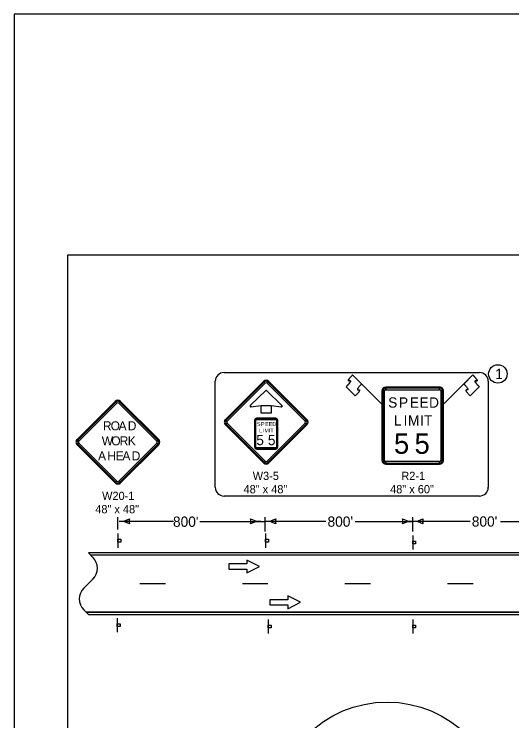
# Model space of a CAD drawing. Extents: x -2135039 to 114557, y -2139150 to -409929.
# Drawn here: x -2135039 to -2134068, y -2137945 to -2136566 of the extents above; entities that cross this region are included whole.
import ezdxf

# ---------------------------------------------------------------- set-up
doc = ezdxf.new("R2010")
doc.units = 0
for name, color, linetype in [('dsnDOTLogo', 7, 'Continuous'), ('dsnStdLabel', 7, 'Continuous'), ('dsnStdLineWork', 7, 'Continuous'), ('dsnStdNote', 7, 'Continuous'), ('dsnStdShading', 7, 'Continuous'), ('Level 1', 7, 'Continuous'), ('StdDimension', 7, 'Continuous')]:
    doc.layers.add(name, color=color, linetype=linetype)

msp = doc.modelspace()

# ---------------------------------------------------------------- linework, layer by layer
at = {"layer": 'dsnDOTLogo'}
msp.add_lwpolyline([(-2135038.9, -2139150.4), (-2131694.9, -2139150.4), (-2131694.9, -2136566.4), (-2135038.9, -2136566.4)], close=True, dxfattribs=at)
at = {"layer": 'dsnStdLabel'}
for p, q in [((-2134552.7, -2137282.5), (-2134626.9, -2137356.7)), ((-2134467.8, -2137356.7), (-2134542.1, -2137282.5)), ((-2134321.5, -2137327.3), (-2134378.8, -2137270)), ((-2134378.8, -2137270), (-2134361.1, -2137287.7)), ((-2134201.5, -2137327.3), (-2134144.2, -2137270)), ((-2134144.2, -2137270), (-2134161.9, -2137287.7)), ((-2134551.4, -2137283.8), (-2134549.2, -2137286)), ((-2134545.6, -2137286), (-2134543.4, -2137283.8)), ((-2134391.2, -2137293), (-2134373.5, -2137310.7)), ((-2134373.5, -2137310.7), (-2134391.2, -2137293)), ((-2134209, -2137293.8), (-2134314, -2137293.8)), ((-2134314, -2137298.8), (-2134314, -2137295.7)), ((-2134209, -2137295.7), (-2134209, -2137298.8)), ((-2134131.8, -2137293), (-2134149.5, -2137310.7)), ((-2134149.5, -2137310.7), (-2134131.8, -2137293)), ((-2134321.5, -2137301.3), (-2134321.5, -2137436.3)), ((-2134319.6, -2137301.3), (-2134316.5, -2137301.3)), ((-2134206.5, -2137301.3), (-2134203.4, -2137301.3)), ((-2134201.5, -2137436.3), (-2134201.5, -2137301.3)), ((-2134841.9, -2137321.5), (-2134916.1, -2137395.7)), ((-2134840.6, -2137322.8), (-2134838.4, -2137325)), ((-2134834.8, -2137325), (-2134832.6, -2137322.8)), ((-2134757, -2137395.7), (-2134831.3, -2137321.5)), ((-2134577.4, -2137330.8), (-2134578.3, -2137329.9)), ((-2134577.2, -2137332), (-2134577.4, -2137330.8)), ((-2134517.4, -2137330.8), (-2134517.5, -2137332)), ((-2134516.5, -2137329.9), (-2134517.4, -2137330.8)), ((-2134623.4, -2137360.3), (-2134625.6, -2137358.1)), ((-2134625.6, -2137366), (-2134623.4, -2137363.8)), ((-2134569.9, -2137358.3), (-2134569.9, -2137410.8)), ((-2134569, -2137358.3), (-2134567.4, -2137358.3)), ((-2134528.6, -2137354.5), (-2134566.1, -2137354.5)), ((-2134566.1, -2137357), (-2134566.1, -2137355.5)), ((-2134528.6, -2137355.5), (-2134528.6, -2137357)), ((-2134527.4, -2137358.3), (-2134525.8, -2137358.3)), ((-2134524.9, -2137410.8), (-2134524.9, -2137358.3)), ((-2134469.2, -2137358.1), (-2134471.4, -2137360.3)), ((-2134471.4, -2137363.8), (-2134469.2, -2137366)), ((-2134626.9, -2137367.3), (-2134552.7, -2137441.6)), ((-2134542.1, -2137441.6), (-2134467.8, -2137367.3)), ((-2134916.1, -2137406.3), (-2134841.9, -2137480.6)), ((-2134912.6, -2137399.2), (-2134914.8, -2137397)), ((-2134914.8, -2137405), (-2134912.6, -2137402.8)), ((-2134831.3, -2137480.6), (-2134757, -2137406.3)), ((-2134758.4, -2137397), (-2134760.6, -2137399.2)), ((-2134760.6, -2137402.8), (-2134758.4, -2137405)), ((-2134567.4, -2137410.8), (-2134569, -2137410.8)), ((-2134566.1, -2137413.6), (-2134566.1, -2137412)), ((-2134566.1, -2137414.5), (-2134528.6, -2137414.5)), ((-2134528.6, -2137412), (-2134528.6, -2137413.6)), ((-2134525.8, -2137410.8), (-2134527.4, -2137410.8)), ((-2134549.2, -2137438.1), (-2134551.4, -2137440.3)), ((-2134543.4, -2137440.3), (-2134545.6, -2137438.1)), ((-2134316.5, -2137436.3), (-2134319.6, -2137436.3)), ((-2134314, -2137441.9), (-2134314, -2137438.8)), ((-2134314, -2137443.8), (-2134209, -2137443.8)), ((-2134209, -2137438.8), (-2134209, -2137441.9)), ((-2134203.4, -2137436.3), (-2134206.5, -2137436.3)), ((-2134838.4, -2137477), (-2134840.6, -2137479.2)), ((-2134832.6, -2137479.2), (-2134834.8, -2137477)), ((-2134836.6, -2137579.4), (-2134836.6, -2137606.9)), ((-2134548.7, -2137579.4), (-2134548.7, -2137606.9)), ((-2134261.5, -2137583.1), (-2134261.5, -2137610.6)), ((-2134837.9, -2137744.4), (-2134837.9, -2137771.9)), ((-2134543.6, -2137746.9), (-2134543.6, -2137774.4)), ((-2134261.5, -2137746.9), (-2134261.5, -2137774.4))]:
    msp.add_line(p, q, dxfattribs=at)
for points in [[(-2134629.6, -2137265.4), (-2134131.2, -2137265.4)], [(-2134646.6, -2137489.1), (-2134646.6, -2137282.4)], [(-2134114.1, -2137282.4), (-2134114.1, -2137489.1)], [(-2134131.2, -2137506.1), (-2134629.6, -2137506.1)], [(-2134620.1, -2137638.5), (-2134620.1, -2137648.5), (-2134585.1, -2137648.5), (-2134585.1, -2137656), (-2134560.1, -2137643.5), (-2134585.1, -2137631), (-2134585.1, -2137638.5), (-2134620.1, -2137638.5)], [(-2134540.1, -2137708.4), (-2134540.1, -2137718.4), (-2134505.2, -2137718.4), (-2134505.2, -2137725.9), (-2134480.2, -2137713.4), (-2134505.2, -2137700.9), (-2134505.2, -2137708.4), (-2134540.1, -2137708.4)]]:
    msp.add_lwpolyline(points, dxfattribs=at)
for points in [[(-2134551.4, -2137283.8), (-2134625.6, -2137358.1), (-2134623.4, -2137360.3), (-2134549.2, -2137286), (-2134551.4, -2137283.8)], [(-2134469.2, -2137358.1), (-2134543.4, -2137283.8), (-2134545.6, -2137286), (-2134471.4, -2137360.3), (-2134469.2, -2137358.1)], [(-2134209, -2137295.7), (-2134314, -2137295.7), (-2134314, -2137298.8), (-2134209, -2137298.8), (-2134209, -2137295.7)], [(-2134547.4, -2137299.5), (-2134578.3, -2137329.9), (-2134577.4, -2137330.8), (-2134577.2, -2137332), (-2134557.4, -2137329.5), (-2134537.4, -2137329.5), (-2134517.5, -2137332), (-2134517.4, -2137330.8), (-2134516.5, -2137329.9), (-2134547.4, -2137299.5)], [(-2134319.6, -2137301.3), (-2134319.6, -2137436.3), (-2134316.5, -2137436.3), (-2134316.5, -2137301.3), (-2134319.6, -2137301.3)], [(-2134203.4, -2137436.3), (-2134203.4, -2137301.3), (-2134206.5, -2137301.3), (-2134206.5, -2137436.3), (-2134203.4, -2137436.3)], [(-2134840.6, -2137322.8), (-2134914.8, -2137397), (-2134912.6, -2137399.2), (-2134838.4, -2137325), (-2134840.6, -2137322.8)], [(-2134758.4, -2137397), (-2134832.6, -2137322.8), (-2134834.8, -2137325), (-2134760.6, -2137399.2), (-2134758.4, -2137397)], [(-2134537.4, -2137344.5), (-2134557.4, -2137344.5), (-2134557.4, -2137329.5), (-2134537.4, -2137329.5), (-2134537.4, -2137344.5)], [(-2134625.6, -2137366), (-2134551.4, -2137440.3), (-2134549.2, -2137438.1), (-2134623.4, -2137363.8), (-2134625.6, -2137366)], [(-2134569, -2137358.3), (-2134569, -2137410.8), (-2134567.4, -2137410.8), (-2134567.4, -2137358.3), (-2134569, -2137358.3)], [(-2134528.6, -2137355.5), (-2134566.1, -2137355.5), (-2134566.1, -2137357), (-2134528.6, -2137357), (-2134528.6, -2137355.5)], [(-2134543.4, -2137440.3), (-2134469.2, -2137366), (-2134471.4, -2137363.8), (-2134545.6, -2137438.1), (-2134543.4, -2137440.3)], [(-2134525.8, -2137410.8), (-2134525.8, -2137358.3), (-2134527.4, -2137358.3), (-2134527.4, -2137410.8), (-2134525.8, -2137410.8)], [(-2134914.8, -2137405), (-2134840.6, -2137479.2), (-2134838.4, -2137477), (-2134912.6, -2137402.8), (-2134914.8, -2137405)], [(-2134832.6, -2137479.2), (-2134758.4, -2137405), (-2134760.6, -2137402.8), (-2134834.8, -2137477), (-2134832.6, -2137479.2)], [(-2134566.1, -2137413.6), (-2134528.6, -2137413.6), (-2134528.6, -2137412), (-2134566.1, -2137412), (-2134566.1, -2137413.6)], [(-2134314, -2137441.9), (-2134209, -2137441.9), (-2134209, -2137438.8), (-2134314, -2137438.8), (-2134314, -2137441.9)], [(-2134836.6, -2137595.9), (-2134836.6, -2137590.2), (-2134830.9, -2137590.2), (-2134830.9, -2137595.9)], [(-2134548.6, -2137595.9), (-2134548.6, -2137590.2), (-2134543, -2137590.2), (-2134543, -2137595.9)], [(-2134261.4, -2137599.6), (-2134261.4, -2137594), (-2134255.8, -2137594), (-2134255.8, -2137599.6)], [(-2134837.8, -2137760.8), (-2134837.8, -2137755.2), (-2134832.1, -2137755.2), (-2134832.1, -2137760.8)], [(-2134543.5, -2137763.4), (-2134543.5, -2137757.7), (-2134537.9, -2137757.7), (-2134537.9, -2137763.4)], [(-2134261.4, -2137763.4), (-2134261.4, -2137757.7), (-2134255.8, -2137757.7), (-2134255.8, -2137763.4)]]:
    msp.add_lwpolyline(points, close=True, dxfattribs=at)
msp.add_circle((-2134311.5, -2138129.5), 221.6, dxfattribs=at)
for centre, radius, start, end in [((-2134629.6, -2137282.4), 17, 90, 180), ((-2134131.2, -2137282.4), 17, 0, 90), ((-2134547.4, -2137287.8), 7.5, 45, 134.9997), ((-2134547.4, -2137287.8), 5.62, 45, 134.9997), ((-2134547.4, -2137287.8), 2.5, 45, 134.9997), ((-2134314, -2137301.3), 7.5, 90.0002, 179.9998), ((-2134314, -2137301.3), 5.62, 90.0002, 179.9998), ((-2134209, -2137301.3), 7.5, 0, 90.0002), ((-2134209, -2137301.3), 5.62, 0, 90.0002), ((-2134314, -2137301.3), 2.5, 90.0002, 179.9998), ((-2134209, -2137301.3), 2.5, 0, 90.0002), ((-2134836.6, -2137326.8), 7.5, 45, 134.9997), ((-2134836.6, -2137326.8), 5.62, 45, 134.9997), ((-2134836.6, -2137326.8), 2.5, 45, 134.9997), ((-2134577.4, -2137330.8), 1.25, 134.9997, 277.1529), ((-2134517.4, -2137330.8), 1.25, 262.8473, 44.9998), ((-2134621.6, -2137362), 7.5, 134.9997, 225), ((-2134621.6, -2137362), 5.62, 134.9997, 225), ((-2134621.6, -2137362), 2.5, 134.9997, 225), ((-2134566.1, -2137358.3), 3.75, 90.0002, 179.9998), ((-2134566.1, -2137358.3), 2.81, 90.0002, 179.9998), ((-2134566.1, -2137358.3), 1.25, 90.0002, 179.9998), ((-2134528.6, -2137358.3), 3.75, 0, 90.0002), ((-2134528.6, -2137358.3), 2.81, 0, 90.0002), ((-2134528.6, -2137358.3), 1.25, 0, 90.0002), ((-2134473.1, -2137362), 2.5, 315.0002, 44.9998), ((-2134473.1, -2137362), 5.62, 315.0002, 44.9998), ((-2134473.1, -2137362), 7.5, 315.0002, 44.9998), ((-2134910.8, -2137401), 7.5, 134.9997, 225), ((-2134910.8, -2137401), 5.62, 134.9997, 225), ((-2134910.8, -2137401), 2.5, 134.9997, 225), ((-2134762.3, -2137401), 2.5, 315.0002, 44.9998), ((-2134762.3, -2137401), 5.62, 315.0002, 44.9998), ((-2134762.3, -2137401), 7.5, 315.0002, 44.9998), ((-2134566.1, -2137410.8), 3.75, 179.9998, 270.0001), ((-2134566.1, -2137410.8), 2.81, 179.9998, 270.0001), ((-2134566.1, -2137410.8), 1.25, 179.9998, 270.0001), ((-2134528.6, -2137410.8), 3.75, 270.0001, 0.0003), ((-2134528.6, -2137410.8), 2.81, 270.0001, 0.0003), ((-2134528.6, -2137410.8), 1.25, 270.0001, 0.0003), ((-2134547.4, -2137436.3), 7.5, 225, 315.0002), ((-2134547.4, -2137436.3), 5.62, 225, 315.0002), ((-2134547.4, -2137436.3), 2.5, 225, 315.0002), ((-2134314, -2137436.3), 7.5, 179.9998, 270.0001), ((-2134314, -2137436.3), 5.62, 179.9998, 270.0001), ((-2134314, -2137436.3), 2.5, 179.9998, 270.0001), ((-2134209, -2137436.3), 7.5, 270.0001, 0.0003), ((-2134209, -2137436.3), 5.62, 270.0001, 0.0003), ((-2134209, -2137436.3), 2.5, 270.0001, 0.0003), ((-2134836.6, -2137475.3), 7.5, 225, 315.0002), ((-2134836.6, -2137475.3), 5.62, 225, 315.0002), ((-2134836.6, -2137475.3), 2.5, 225, 315.0002), ((-2134629.6, -2137489.1), 17, 180, 270), ((-2134131.2, -2137489.1), 17, 270, 0)]:
    msp.add_arc(centre, radius, start, end, dxfattribs=at)
for points in [[(-2134378.8, -2137270), (-2134391.2, -2137282.4), (-2134378.8, -2137280.6), (-2134391.2, -2137293)], [(-2134391.2, -2137293), (-2134378.8, -2137280.6), (-2134391.2, -2137282.4), (-2134378.8, -2137270)], [(-2134144.2, -2137270), (-2134131.8, -2137282.4), (-2134144.2, -2137280.6), (-2134131.8, -2137293)], [(-2134131.8, -2137293), (-2134144.2, -2137280.6), (-2134131.8, -2137282.4), (-2134144.2, -2137270)], [(-2134361.1, -2137287.7), (-2134373.5, -2137300.1), (-2134361.2, -2137298.3), (-2134373.5, -2137310.7)], [(-2134361.1, -2137287.7), (-2134373.5, -2137300.1), (-2134361.2, -2137298.3), (-2134373.5, -2137310.7)], [(-2134161.9, -2137287.7), (-2134149.5, -2137300.1), (-2134161.9, -2137298.3), (-2134149.5, -2137310.7)], [(-2134161.9, -2137287.7), (-2134149.5, -2137300.1), (-2134161.9, -2137298.3), (-2134149.5, -2137310.7)]]:
    msp.add_open_spline(points, degree=2, dxfattribs=at)
at = {"layer": 'dsnStdLineWork'}
for p, q in [((-2134885.4, -2137625.7), (-2134894.2, -2137616.9)), ((-2134890.2, -2137620.9), (-2133281.9, -2137620.9)), ((-2134903, -2137685.7), (-2134885.4, -2137668.1)), ((-2134894.2, -2137736.9), (-2134903, -2137728.1)), ((-2134898.2, -2137732.9), (-2132869.8, -2137732.9))]:
    msp.add_line(p, q, dxfattribs=at)
for points in [[(-2134793.8, -2137676.5), (-2134743.8, -2137676.5)], [(-2134593.8, -2137676.5), (-2134543.9, -2137676.5)], [(-2134393.9, -2137676.5), (-2134343.9, -2137676.5)], [(-2134393.9, -2137676.9), (-2134343.9, -2137676.9)], [(-2134193.9, -2137676.5), (-2134143.9, -2137676.5)], [(-2134193.9, -2137676.9), (-2134143.9, -2137676.9)]]:
    msp.add_lwpolyline(points, dxfattribs=at)
for centre, start, end in [((-2134906.6, -2137646.9), 315, 45), ((-2134881.8, -2137706.9), 135, 225)]:
    msp.add_arc(centre, 30, start, end, dxfattribs=at)
at = {"layer": 'dsnStdNote'}
msp.add_circle((-2134095.5, -2137268.1), 18, dxfattribs=at)
at = {"layer": 'dsnStdShading'}
for p, q in [((-2133849.7, -2137616.9), (-2134894.2, -2137616.9)), ((-2134894.2, -2137616.9), (-2134885.4, -2137625.7)), ((-2133857.1, -2137616.9), (-2134894.2, -2137616.9)), ((-2134890.2, -2137620.9), (-2133857.1, -2137620.9)), ((-2134885.4, -2137668.1), (-2134903, -2137685.7)), ((-2134903, -2137728.1), (-2134898.2, -2137732.9)), ((-2133102.6, -2137732.9), (-2134898.2, -2137732.9)), ((-2134898.2, -2137732.9), (-2134894.2, -2137736.9)), ((-2134898.2, -2137732.9), (-2133681, -2137732.9)), ((-2134894.2, -2137736.9), (-2133075.9, -2137736.9)), ((-2134894.2, -2137736.9), (-2133104.4, -2137736.9))]:
    msp.add_line(p, q, dxfattribs=at)
for points in [[(-2134894.2, -2137616.9), (-2134890.2, -2137620.9), (-2134890.2, -2137620.9)], [(-2134898.2, -2137732.9), (-2134898.2, -2137732.9)], [(-2134898.2, -2137732.9), (-2134898.2, -2137732.9)]]:
    msp.add_lwpolyline(points, dxfattribs=at)
for centre, start, end in [((-2134906.6, -2137646.9), 315, 45), ((-2134881.8, -2137706.9), 135, 225)]:
    msp.add_arc(centre, 30, start, end, dxfattribs=at)
at = {"layer": 'Level 1'}
msp.add_lwpolyline([(-2134934.4, -2137035.9), (-2131799.4, -2137035.9), (-2131799.4, -2139045.9), (-2134934.4, -2139045.9)], close=True, dxfattribs=at)
at = {"layer": 'StdDimension'}
for p, q in [((-2134836.6, -2137571.4), (-2134836.6, -2137547.4)), ((-2134728.4, -2137555.5), (-2134833.8, -2137555.5)), ((-2134676.5, -2137555.5), (-2134549.1, -2137555.5)), ((-2134549.1, -2137575.1), (-2134549.1, -2137547.4)), ((-2134431.3, -2137555.5), (-2134549.1, -2137555.5)), ((-2134373.9, -2137555.5), (-2134261.5, -2137555.5)), ((-2134261.5, -2137575.1), (-2134261.5, -2137547.4)), ((-2134149.7, -2137555.5), (-2134261.5, -2137555.5)), ((-2134090.3, -2137555.5), (-2133973.9, -2137555.5))]:
    msp.add_line(p, q, dxfattribs=at)
for centre, radius, start, end in [((-2134833.8, -2137513), 42.5, 270, 298.0725), ((-2134833.8, -2137598), 42.5, 61.9275, 90), ((-2134798.2, -2137555.5), 16.4, 162.2666, 197.7334), ((-2134593.4, -2137555.5), 16.4, 342.2666, 17.7333), ((-2134557.8, -2137513), 42.5, 241.9275, 270), ((-2134557.8, -2137598), 42.5, 90, 118.0725), ((-2134548.7, -2137513), 42.5, 270, 298.0725), ((-2134548.7, -2137598), 42.5, 61.9275, 90), ((-2134513.1, -2137555.5), 16.4, 162.2666, 197.7334), ((-2134297.1, -2137555.5), 16.4, 342.2666, 17.7333), ((-2134261.5, -2137513), 42.5, 241.9275, 270), ((-2134261.5, -2137598), 42.5, 90, 118.0725), ((-2134261.5, -2137513), 42.5, 270, 298.0725), ((-2134261.5, -2137598), 42.5, 61.9275, 90), ((-2134225.9, -2137555.5), 16.4, 162.2666, 197.7334)]:
    msp.add_arc(centre, radius, start, end, dxfattribs=at)

# ---------------------------------------------------------------- texts
at = {"layer": 'dsnStdLabel'}
for s, height, p in [('S', 20, (-2134309.4, -2137333.8)), ('P', 20, (-2134288.3, -2137333.8)), ('E', 20, (-2134267.2, -2137333.8)), ('E', 20, (-2134248.4, -2137333.8)), ('D', 20, (-2134229.6, -2137333.8)), ('L', 20, (-2134298.1, -2137368.8)), ('I', 20, (-2134279.3, -2137368.8)), ('M', 20, (-2134270.7, -2137368.8)), ('I', 20, (-2134247.1, -2137368.8)), ('T', 20, (-2134239.6, -2137368.8)), ('R', 17.5, (-2134865.8, -2137377.9)), ('O', 17.5, (-2134850.7, -2137377.9)), ('A', 17.5, (-2134835.2, -2137377.9)), ('D', 17.5, (-2134817.3, -2137377.9)), ('S', 7.5, (-2134565.3, -2137369.5)), ('P', 7.5, (-2134557.4, -2137369.5)), ('E', 7.5, (-2134549.5, -2137369.5)), ('E', 7.5, (-2134542.5, -2137369.5)), ('D', 7.5, (-2134535.4, -2137369.5)), ('L', 7.5, (-2134561.1, -2137382)), ('I', 7.5, (-2134554.1, -2137382)), ('M', 7.5, (-2134550.8, -2137382)), ('I', 7.5, (-2134542, -2137382)), ('T', 7.5, (-2134539.2, -2137382)), ('W', 17.5, (-2134868, -2137407.3)), ('O', 17.5, (-2134849.4, -2137407.3)), ('R', 17.5, (-2134833, -2137407.3)), ('K', 17.5, (-2134817.2, -2137407.3)), ('5', 20, (-2134566.6, -2137407)), ('5', 20, (-2134544.1, -2137407)), ('5', 40, (-2134298.1, -2137423.8)), ('5', 40, (-2134258, -2137423.8)), ('A', 17.5, (-2134875.3, -2137436.6)), ('H', 17.5, (-2134857.1, -2137436.6)), ('E', 17.5, (-2134840.9, -2137436.6)), ('A', 17.5, (-2134827.8, -2137436.6)), ('D', 17.5, (-2134809.6, -2137436.6)), ('W3-5', 16, (-2134573.6, -2137474.8)), ('R2-1', 16, (-2134283.7, -2137474.8)), ('48" x 48"', 16, (-2134591.5, -2137500.8)), ('48" x 60"', 16, (-2134305.6, -2137500.8)), ('W20-1', 16, (-2134867.4, -2137513.8)), ('48" x 48"', 16, (-2134880.7, -2137539.8))]:
    msp.add_text(s, height=height, dxfattribs=at).set_placement(p)
at = {"layer": 'dsnStdNote'}
msp.add_text('1', height=20, dxfattribs=at).set_placement((-2134100.7, -2137278.1))
at = {"layer": 'StdDimension'}
for p in [(-2134146.3, -2137565.8), (-2134729.1, -2137566.2), (-2134427.7, -2137566)]:
    msp.add_text("800'", height=20, dxfattribs=at).set_placement(p)

doc.saveas('drawing.dxf')
